// Mitsubishi GX Works2 project: 6个灯循环顺起逆停隔1秒（位移指令）   PLC: FX3U/FX3UC

PROGRAM MAIN
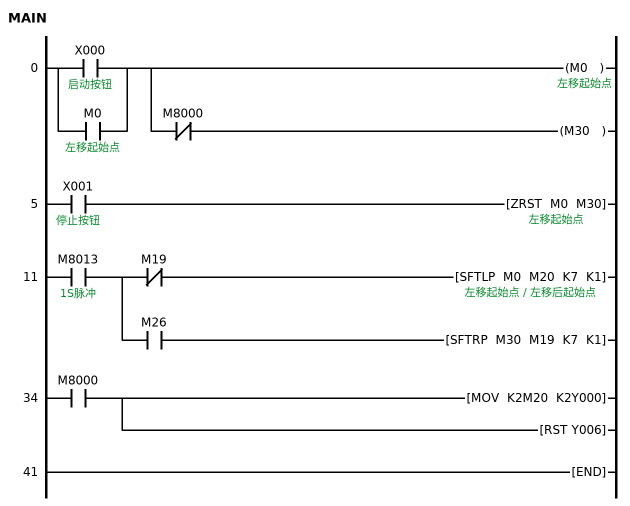
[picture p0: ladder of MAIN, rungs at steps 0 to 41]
0     LD      X000  ; 启动按钮
      OR      M0  ; 左移起始点
      OUT     M0  ; 左移起始点
      ANI     M8000
      OUT     M30
        [note] 永远不通
5     LD      X001  ; 停止按钮
      ZRST    M0 M30
11    LD      M8013  ; 1S脉冲
      MPS
      ANI     M19
      SFTLP   M0 M20 K7 K1  ; 左移后起始点
      MPP
      AND     M26
      SFTRP   M30 M19 K7 K1
34    LD      M8000
      MOV     K2M20 K2Y000
      RST     Y006
41    END
END_PROGRAM

// device comments not shown above
M6  ; 左移后起始点
M12  ; 位移的第七位
